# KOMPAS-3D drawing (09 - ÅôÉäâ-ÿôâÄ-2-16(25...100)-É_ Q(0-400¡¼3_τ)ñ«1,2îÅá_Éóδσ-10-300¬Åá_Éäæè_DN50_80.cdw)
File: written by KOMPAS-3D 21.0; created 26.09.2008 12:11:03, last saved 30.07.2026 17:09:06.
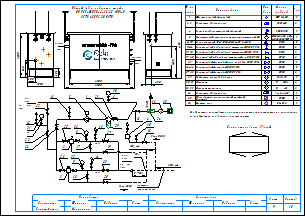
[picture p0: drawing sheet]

Sheets 1-2: A3, landscape

Document properties: Наименование: Макро:21; Автор: RaskoAdmin; Форматы листов документа: 2xA3; Полное имя файла: \\ur38nt01\Departments\КТО\КБ ПУРДГ\Заявки\Прайс-лист на типовые шкафы ГРПШ\ПУРДГ_стандарт_30_04_2026\ПУРДГ с РДСК\ПУРДГ-ШУГО-2-16(25...100)-Р_ Q(0-400нм3_ч)до1,2МПа_Рвых-10-300кПа_РДСК_DN50_80.cdw

Title block, sheet 1: Наименование: Пункт учета газа / ПУГ-Ш-400-Р / ЛГТИ.485922.001ТУ; designation: ЛГТИ.03.4411141; sheet number: 1; Количество листов документа: 2; organisation: ООО "ЭЛЬСТЕР Газэлектроника"; Форматы листов документа: A3; stored path: C:\Рабочие документы\Компас\ПУГ\Схема.cdw; Разработал: Устинов; Проверил: Кошкин; Утвердил: Кошкин
Title block, sheet 2: sheet number: 2; stored path: D:\Рабочие документы\Заявки\ПУРДГ\ПУРДГ-ШУЭО-2-100-Р 4411220.cdw; designation, second copy: ЛГТИ.03.4411141-

Views: Вид 1, Вид 2
Referenced files: wcvoit.frw
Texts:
  Normal
  Общий вид и габариты шкафа
  ПУРДГ-ШУГО-2-16(25...100)-Р
  DN80
  Выход газа
  DN50
  Вход газа
  logo-rasko-ge.png
  DN 1
  местное
  сопротивление
  Римп DN20
  Выход
  газа
  Р=     кПа
  Вход
  Р=       МПа
  PDI
  DN20
  № на
  схеме
  Усл.
  обозн.
  Марка
  (модель)
  Кол.
  Фильтр газовый фланцевый
  ФГ 16-50
  Регулятор давления газа
  РДСК-50
  Клапан предохранительный сбросной
  КПС DN20
  Измерительный комплекс с ротационным счетчиком Ду50
  СГ-ЭК-Р-(0,2...2,0)-
  Кран кнопочный VE-РАСКО-НЗ-1,6-G1/2-М20
  DN15
  Кран шаровой "под приварку" штуцерный DN20 PN16
  Кран шаровой "под приварку" штуцерный DN15 PN16
  Кран шаровой "под приварку" штуцерный п/п DN20 PN16
  Кран шаровой фланцевый с мех. приводом DN50 PN16
  Кран шаровой фланцевый DN50 PN16
  Кран шаровой фланцевый DN80 PN16
  Индикатор перепада давления
  Манометр
  Манометр-напоромер
  Обогреватель газогорелочный шкафной
  (Эльтон")
  Счетчик газа
  Delta 15
  0...     МПа
  0...     кПа
  Venio-A-15
  ОГШН
  BK-G1,6
  Схема открывания дверей
  Предприятие изготовитель может заменять комплектующие на аналогичные,
  не ухудшающие заявленных характеристик.
  Должность
  Конструктор
  Фамилия
  Подпись
  Дата
  Согласовано
  Максимкин
  Лист
  Листов
  POLYLINE_STYLE_0.18_RGB_0_0_0
  POLYLINE_STYLE_0.50_RGB_0_0_0
  POLYLINE_STYLE_0.34_RGB_0_0_0
  PHANTOM_RGB_0_0_0_SC_1_THICK_0.18
  K5LT_THIN_RGB_0_0_0_THICK_0.18
  K5LT32769_RGB_0_0_0_THICK_0.18
  K5LT12_RGB_0_0_0_SC_1_THICK_0.18
  K5LT_DASHED_RGB_0_0_0_SC_1_THICK_0.18
  ACISOTGL_RGB_0_0_0_SC_0.8_THICK_0.25
  CONTINUOUS_RGB_0_127_31_THICK_0.3
  CONTINUOUS_RGB_0_0_255_THICK_0.35
  CONTINUOUS_RGB_255_0_0_THICK_0.35
  POLYLINE_STYLE_0.25_RGB_0_0_0
  CONTINUOUS_RGB_0_0_0_THICK_0.5
  POLYLINE_STYLE_0.35_RGB_0_0_255
  CONTINUOUS_RGB_0_0_0_THICK_0.4
  CONTINUOUS_RGB_0_0_0_THICK_0.35
  НЕВИДИМАЯ_RGB_0_0_0_SC_0.3_THICK_0.25
  СONTINUOUS_RGB_0_0_0_THICK_0.25
  ОСЕВАЯ2_RGB_248_153_30_SC_0.3_THICK_0.25
  Без оформления
Dimensions and other numbers on the sheet: 1; 1500; 250; 300; 1050; 550; 305; 2300; 4130; 2000; 2600; 5,,,7DN 1; 7; 31; 12; 22; 23; 24; 11; 5; 21; 6; 30; 25; 32; 8; 2; 17; 13; 27; 19; 4; 10; 15; 26; 33; 9; 3; 18; 14; 28; 20; 29; 16; 34; 35; 36; 2, 3; 6-10; 11-16; 17, 18; 19, 20; 22-26; 27, 28; 30, 31; 32, 33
